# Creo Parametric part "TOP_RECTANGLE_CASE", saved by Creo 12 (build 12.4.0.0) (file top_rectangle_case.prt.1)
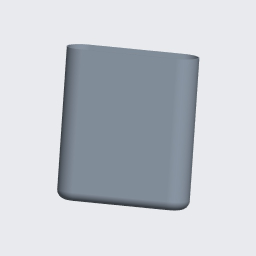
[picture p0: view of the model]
Units: Inch lbm Second (Pro/E Default); INCH, POUND, SECS

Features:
  1. datum plane "RIGHT"
  2. datum plane "TOP"
  3. datum plane "FRONT"
  4. coordinate system
  5. protrusion
  6. round
  7. round
  8. cut
  9. datum plane "DTM1"
  10. datum plane "DTM2"
  11. protrusion
  12. round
